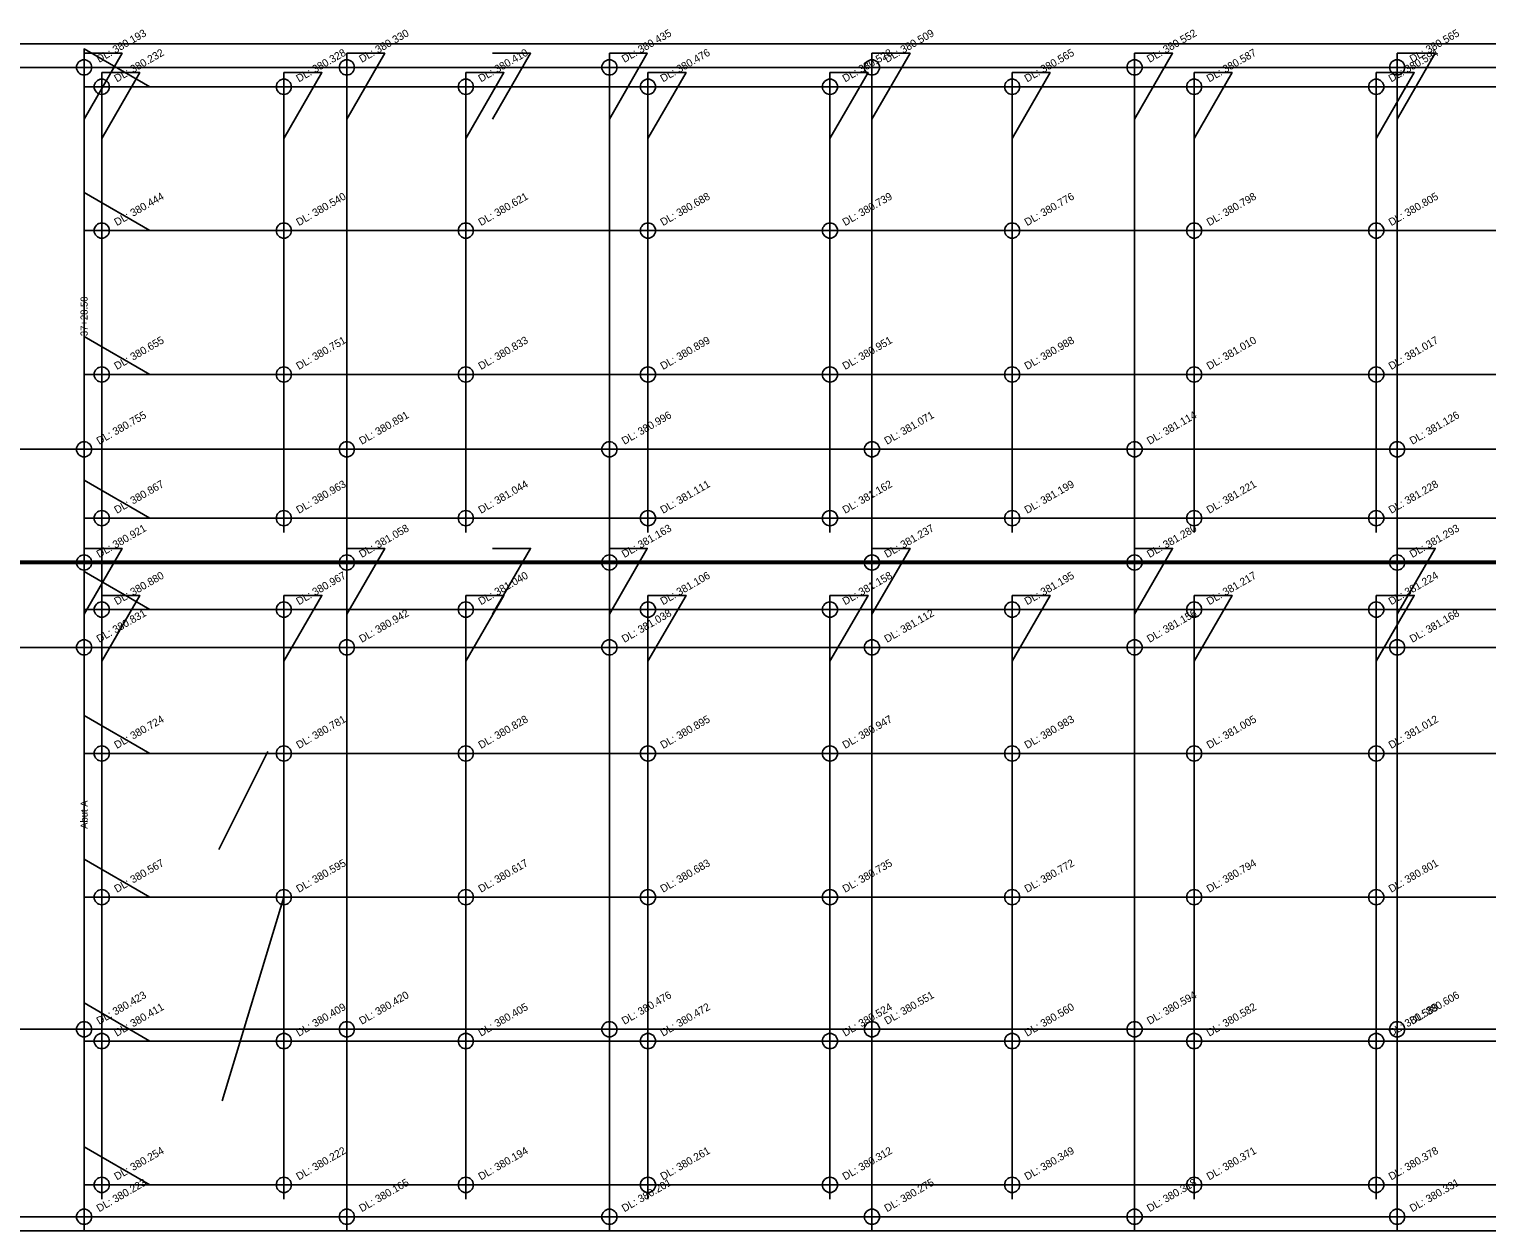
# Model space of a CAD drawing. Extents: x 100440 to 101111, y 50226 to 50315.
# Drawn here: x 100555.6 to 100658.7, y 50225.9 to 50310.8 of the extents above; entities that cross this region are included whole.
import ezdxf

# ---------------------------------------------------------------- set-up
doc = ezdxf.new("R2010")
doc.units = 0
for name, color, linetype in [('Level 1', 7, 'Continuous'), ('Level 10', 7, 'Continuous'), ('Level 21', 7, 'Continuous'), ('Level 23', 7, 'Continuous')]:
    doc.layers.add(name, color=color, linetype=linetype)

msp = doc.modelspace()

# ---------------------------------------------------------------- linework, layer by layer
at = {"layer": 'Level 1'}
for p, q in [((100559.5, 50306.77), (101034.5, 50306.77)), ((100559.5, 50296.6), (101034.5, 50296.6)), ((100560.75, 50288.14), (100560.75, 50258.14)), ((100560.75, 50288.14), (100560.75, 50258.14)), ((100559.5, 50286.43), (101034.5, 50286.43)), ((100559.5, 50276.27), (101034.5, 50276.27)), ((100559.5, 50269.81), (101034.5, 50269.81)), ((100559.5, 50259.64), (101034.5, 50259.64)), ((100559.5, 50249.48), (101034.5, 50249.48)), ((100559.5, 50239.31), (101034.5, 50239.31)), ((100559.5, 50229.14), (101034.5, 50229.14))]:
    msp.add_line(p, q, dxfattribs=at)
for points in [[(100564.16, 50306.77), (100559.5, 50309.45), (100559.5, 50306.77)], [(100564.16, 50296.6), (100559.5, 50299.29), (100559.5, 50296.6)], [(100564.16, 50286.43), (100559.5, 50289.12), (100559.5, 50286.43)], [(100564.16, 50276.27), (100559.5, 50278.95), (100559.5, 50276.27)], [(100564.16, 50269.81), (100559.5, 50272.5), (100559.5, 50269.81)], [(100564.16, 50259.64), (100559.5, 50262.33), (100559.5, 50259.64)], [(100564.16, 50249.48), (100559.5, 50252.16), (100559.5, 50249.48)], [(100564.16, 50239.31), (100559.5, 50242), (100559.5, 50239.31)], [(100564.16, 50229.14), (100559.5, 50231.83), (100559.5, 50229.14)]]:
    msp.add_lwpolyline(points, dxfattribs=at)
at = {"layer": 'Level 10'}
for points in [[(100559.5, 50309.14), (100559.5, 50272.14)], [(100559.5, 50304.49), (100562.19, 50309.14), (100559.5, 50309.14)], [(100578.08, 50309.14), (100578.08, 50272.14)], [(100578.08, 50304.49), (100580.76, 50309.14), (100578.08, 50309.14)], [(100588.39, 50304.49), (100591.08, 50309.14), (100588.39, 50309.14)], [(100596.65, 50309.14), (100596.65, 50272.14)], [(100596.65, 50304.49), (100599.33, 50309.14), (100596.65, 50309.14)], [(100615.22, 50309.14), (100615.22, 50272.14)], [(100615.22, 50304.49), (100617.91, 50309.14), (100615.22, 50309.14)], [(100633.79, 50309.14), (100633.79, 50272.14)], [(100633.79, 50304.49), (100636.48, 50309.14), (100633.79, 50309.14)], [(100652.36, 50309.14), (100652.36, 50272.14)], [(100652.36, 50304.49), (100655.05, 50309.14), (100652.36, 50309.14)], [(100560.75, 50307.77), (100560.75, 50275.27)], [(100560.75, 50303.11), (100563.44, 50307.77), (100560.75, 50307.77)], [(100573.63, 50307.77), (100573.63, 50275.27)], [(100573.63, 50303.11), (100576.32, 50307.77), (100573.63, 50307.77)], [(100586.5, 50307.77), (100586.5, 50275.27)], [(100586.5, 50303.11), (100589.19, 50307.77), (100586.5, 50307.77)], [(100599.38, 50307.77), (100599.38, 50275.27)], [(100599.38, 50303.11), (100602.07, 50307.77), (100599.38, 50307.77)], [(100612.25, 50307.77), (100612.25, 50275.27)], [(100612.25, 50303.11), (100614.94, 50307.77), (100612.25, 50307.77)], [(100625.13, 50307.77), (100625.13, 50275.27)], [(100625.13, 50303.11), (100627.82, 50307.77), (100625.13, 50307.77)], [(100638, 50307.77), (100638, 50275.27)], [(100638, 50303.11), (100640.69, 50307.77), (100638, 50307.77)], [(100650.88, 50307.77), (100650.88, 50275.27)], [(100650.88, 50303.11), (100653.57, 50307.77), (100650.88, 50307.77)], [(100559.5, 50274.14), (100559.5, 50225.89)], [(100559.5, 50269.49), (100562.19, 50274.14), (100559.5, 50274.14)], [(100578.08, 50274.14), (100578.08, 50225.89)], [(100578.08, 50269.49), (100580.76, 50274.14), (100578.08, 50274.14)], [(100588.39, 50269.49), (100591.08, 50274.14), (100588.39, 50274.14)], [(100596.65, 50274.14), (100596.65, 50225.89)], [(100596.65, 50269.49), (100599.33, 50274.14), (100596.65, 50274.14)], [(100615.22, 50274.14), (100615.22, 50225.89)], [(100615.22, 50269.49), (100617.91, 50274.14), (100615.22, 50274.14)], [(100633.79, 50274.14), (100633.79, 50225.89)], [(100633.79, 50269.49), (100636.48, 50274.14), (100633.79, 50274.14)], [(100652.36, 50274.14), (100652.36, 50225.89)], [(100652.36, 50269.49), (100655.05, 50274.14), (100652.36, 50274.14)], [(100560.75, 50270.81), (100560.75, 50228.14)], [(100560.75, 50266.16), (100563.44, 50270.81), (100560.75, 50270.81)], [(100573.63, 50270.81), (100573.63, 50228.14)], [(100573.63, 50266.16), (100576.32, 50270.81), (100573.63, 50270.81)], [(100586.5, 50270.81), (100586.5, 50228.14)], [(100586.5, 50266.16), (100589.19, 50270.81), (100586.5, 50270.81)], [(100599.38, 50270.81), (100599.38, 50228.14)], [(100599.38, 50266.16), (100602.07, 50270.81), (100599.38, 50270.81)], [(100612.25, 50270.81), (100612.25, 50228.14)], [(100612.25, 50266.16), (100614.94, 50270.81), (100612.25, 50270.81)], [(100625.13, 50270.81), (100625.13, 50228.14)], [(100625.13, 50266.16), (100627.82, 50270.81), (100625.13, 50270.81)], [(100638, 50270.81), (100638, 50228.14)], [(100638, 50266.16), (100640.69, 50270.81), (100638, 50270.81)], [(100650.88, 50270.81), (100650.88, 50228.14)], [(100650.88, 50266.16), (100653.57, 50270.81), (100650.88, 50270.81)]]:
    msp.add_lwpolyline(points, dxfattribs=at)
for centre in [(100559.5, 50308.14), (100578.08, 50308.14), (100596.65, 50308.14), (100615.22, 50308.14), (100633.79, 50308.14), (100652.36, 50308.14), (100560.75, 50306.77), (100573.63, 50306.77), (100586.5, 50306.77), (100599.38, 50306.77), (100612.25, 50306.77), (100625.13, 50306.77), (100638, 50306.77), (100650.88, 50306.77), (100560.75, 50296.6), (100573.63, 50296.6), (100586.5, 50296.6), (100599.38, 50296.6), (100612.25, 50296.6), (100625.13, 50296.6), (100638, 50296.6), (100650.88, 50296.6), (100560.75, 50286.43), (100573.63, 50286.43), (100586.5, 50286.43), (100599.38, 50286.43), (100612.25, 50286.43), (100625.13, 50286.43), (100638, 50286.43), (100650.88, 50286.43), (100559.5, 50281.14), (100578.08, 50281.14), (100596.65, 50281.14), (100615.22, 50281.14), (100633.79, 50281.14), (100652.36, 50281.14), (100560.75, 50276.27), (100573.63, 50276.27), (100586.5, 50276.27), (100599.38, 50276.27), (100612.25, 50276.27), (100625.13, 50276.27), (100638, 50276.27), (100650.88, 50276.27), (100559.5, 50273.14), (100559.5, 50273.14), (100578.08, 50273.14), (100578.08, 50273.14), (100596.65, 50273.14), (100596.65, 50273.14), (100615.22, 50273.14), (100615.22, 50273.14), (100633.79, 50273.14), (100633.79, 50273.14), (100652.36, 50273.14), (100652.36, 50273.14), (100560.75, 50269.81), (100573.63, 50269.81), (100586.5, 50269.81), (100599.38, 50269.81), (100612.25, 50269.81), (100625.13, 50269.81), (100638, 50269.81), (100650.88, 50269.81), (100559.5, 50267.14), (100578.08, 50267.14), (100596.65, 50267.14), (100615.22, 50267.14), (100633.79, 50267.14), (100652.36, 50267.14), (100560.75, 50259.64), (100573.63, 50259.64), (100586.5, 50259.64), (100599.38, 50259.64), (100612.25, 50259.64), (100625.13, 50259.64), (100638, 50259.64), (100650.88, 50259.64), (100560.75, 50249.48), (100573.63, 50249.48), (100586.5, 50249.48), (100599.38, 50249.48), (100612.25, 50249.48), (100625.13, 50249.48), (100638, 50249.48), (100650.88, 50249.48), (100559.5, 50240.14), (100578.08, 50240.14), (100596.65, 50240.14), (100615.22, 50240.14), (100633.79, 50240.14), (100652.36, 50240.14), (100560.75, 50239.31), (100573.63, 50239.31), (100586.5, 50239.31), (100599.38, 50239.31), (100612.25, 50239.31), (100625.13, 50239.31), (100638, 50239.31), (100650.88, 50239.31), (100560.75, 50229.14), (100573.63, 50229.14), (100586.5, 50229.14), (100599.38, 50229.14), (100612.25, 50229.14), (100625.13, 50229.14), (100638, 50229.14), (100650.88, 50229.14), (100559.5, 50226.89), (100578.08, 50226.89), (100596.65, 50226.89), (100615.22, 50226.89), (100633.79, 50226.89), (100652.36, 50226.89)]:
    msp.add_circle(centre, 0.537, dxfattribs=at)
at = {"layer": 'Level 23'}
for p, q in [((100439.55, 50309.81), (101111.48, 50309.81)), ((100439.55, 50308.14), (101111.48, 50308.14)), ((100559.5, 50288.14), (100559.5, 50258.14)), ((100559.5, 50288.14), (100559.5, 50258.14)), ((100439.55, 50281.14), (101111.48, 50281.14)), ((100439.55, 50273.23), (101111.48, 50273.23)), ((100439.55, 50273.14), (101111.48, 50273.14)), ((100448.2, 50273.14), (101107.51, 50273.14)), ((100448.2, 50273.06), (101107.51, 50273.06)), ((100448.2, 50267.14), (101107.51, 50267.14)), ((100572.5, 50259.77), (100569.03, 50252.85)), ((100573.63, 50249.48), (100569.26, 50235.09)), ((100448.2, 50240.14), (101107.51, 50240.14)), ((100448.2, 50226.89), (101107.51, 50226.89)), ((100448.2, 50225.89), (101107.51, 50225.89))]:
    msp.add_line(p, q, dxfattribs=at)

# ---------------------------------------------------------------- texts
at = {"layer": 'Level 10'}
for s, p in [('DL: 380.193', (100560.57, 50308.45)), ('DL: 380.330', (100579.14, 50308.45)), ('DL: 380.435', (100597.71, 50308.45)), ('DL: 380.509', (100616.28, 50308.45)), ('DL: 380.552', (100634.85, 50308.45)), ('DL: 380.565', (100653.43, 50308.45)), ('DL: 380.232', (100561.82, 50307.07)), ('DL: 380.328', (100574.69, 50307.07)), ('DL: 380.410', (100587.57, 50307.07)), ('DL: 380.476', (100600.44, 50307.07)), ('DL: 380.528', (100613.32, 50307.07)), ('DL: 380.565', (100626.19, 50307.07)), ('DL: 380.587', (100639.07, 50307.07)), ('DL: 380.594', (100651.94, 50307.07)), ('DL: 380.444', (100561.82, 50296.91)), ('DL: 380.540', (100574.69, 50296.91)), ('DL: 380.621', (100587.57, 50296.91)), ('DL: 380.688', (100600.44, 50296.91)), ('DL: 380.739', (100613.32, 50296.91)), ('DL: 380.776', (100626.19, 50296.91)), ('DL: 380.798', (100639.07, 50296.91)), ('DL: 380.805', (100651.94, 50296.91)), ('DL: 380.655', (100561.82, 50286.74)), ('DL: 380.751', (100574.69, 50286.74)), ('DL: 380.833', (100587.57, 50286.74)), ('DL: 380.899', (100600.44, 50286.74)), ('DL: 380.951', (100613.32, 50286.74)), ('DL: 380.988', (100626.19, 50286.74)), ('DL: 381.010', (100639.07, 50286.74)), ('DL: 381.017', (100651.94, 50286.74)), ('DL: 380.755', (100560.57, 50281.45)), ('DL: 380.891', (100579.14, 50281.45)), ('DL: 380.996', (100597.71, 50281.45)), ('DL: 381.071', (100616.28, 50281.45)), ('DL: 381.114', (100634.85, 50281.45)), ('DL: 381.126', (100653.43, 50281.45)), ('DL: 380.867', (100561.82, 50276.57)), ('DL: 380.963', (100574.69, 50276.57)), ('DL: 381.044', (100587.57, 50276.57)), ('DL: 381.111', (100600.44, 50276.57)), ('DL: 381.162', (100613.32, 50276.57)), ('DL: 381.199', (100626.19, 50276.57)), ('DL: 381.221', (100639.07, 50276.57)), ('DL: 381.228', (100651.94, 50276.57)), ('DL: 380.921', (100560.57, 50273.45)), ('DL: 380.921', (100560.57, 50273.45)), ('DL: 381.058', (100579.14, 50273.45)), ('DL: 381.058', (100579.14, 50273.45)), ('DL: 381.163', (100597.71, 50273.45)), ('DL: 381.163', (100597.71, 50273.45)), ('DL: 381.237', (100616.28, 50273.45)), ('DL: 381.237', (100616.28, 50273.45)), ('DL: 381.280', (100634.85, 50273.45)), ('DL: 381.280', (100634.85, 50273.45)), ('DL: 381.293', (100653.43, 50273.45)), ('DL: 381.293', (100653.43, 50273.45)), ('DL: 380.880', (100561.82, 50270.11)), ('DL: 380.967', (100574.69, 50270.11)), ('DL: 381.040', (100587.57, 50270.11)), ('DL: 381.106', (100600.44, 50270.11)), ('DL: 381.158', (100613.32, 50270.11)), ('DL: 381.195', (100626.19, 50270.11)), ('DL: 381.217', (100639.07, 50270.11)), ('DL: 381.224', (100651.94, 50270.11)), ('DL: 380.831', (100560.57, 50267.45)), ('DL: 380.942', (100579.14, 50267.45)), ('DL: 381.038', (100597.71, 50267.45)), ('DL: 381.112', (100616.28, 50267.45)), ('DL: 381.156', (100634.85, 50267.45)), ('DL: 381.168', (100653.43, 50267.45)), ('DL: 380.724', (100561.82, 50259.95)), ('DL: 380.781', (100574.69, 50259.95)), ('DL: 380.828', (100587.57, 50259.95)), ('DL: 380.895', (100600.44, 50259.95)), ('DL: 380.947', (100613.32, 50259.95)), ('DL: 380.983', (100626.19, 50259.95)), ('DL: 381.005', (100639.07, 50259.95)), ('DL: 381.012', (100651.94, 50259.95)), ('DL: 380.567', (100561.82, 50249.78)), ('DL: 380.595', (100574.69, 50249.78)), ('DL: 380.617', (100587.57, 50249.78)), ('DL: 380.683', (100600.44, 50249.78)), ('DL: 380.735', (100613.32, 50249.78)), ('DL: 380.772', (100626.19, 50249.78)), ('DL: 380.794', (100639.07, 50249.78)), ('DL: 380.801', (100651.94, 50249.78)), ('DL: 380.423', (100560.57, 50240.45)), ('DL: 380.420', (100579.14, 50240.45)), ('DL: 380.476', (100597.71, 50240.45)), ('DL: 380.551', (100616.28, 50240.45)), ('DL: 380.594', (100634.85, 50240.45)), ('DL: 380.606', (100653.43, 50240.45)), ('DL: 380.411', (100561.82, 50239.61)), ('DL: 380.409', (100574.69, 50239.61)), ('DL: 380.405', (100587.57, 50239.61)), ('DL: 380.472', (100600.44, 50239.61)), ('DL: 380.524', (100613.32, 50239.61)), ('DL: 380.560', (100626.19, 50239.61)), ('DL: 380.582', (100639.07, 50239.61)), ('DL: 380.589', (100651.94, 50239.61)), ('DL: 380.254', (100561.82, 50229.45)), ('DL: 380.222', (100574.69, 50229.45)), ('DL: 380.194', (100587.57, 50229.45)), ('DL: 380.261', (100600.44, 50229.45)), ('DL: 380.312', (100613.32, 50229.45)), ('DL: 380.349', (100626.19, 50229.45)), ('DL: 380.371', (100639.07, 50229.45)), ('DL: 380.378', (100651.94, 50229.45)), ('DL: 380.223', (100560.57, 50227.2)), ('DL: 380.165', (100579.14, 50227.2)), ('DL: 380.201', (100597.71, 50227.2)), ('DL: 380.275', (100616.28, 50227.2)), ('DL: 380.318', (100634.85, 50227.2)), ('DL: 380.331', (100653.43, 50227.2))]:
    msp.add_text(s, height=0.5373, rotation=30, dxfattribs=at).set_placement(p)
at = {"layer": 'Level 21'}
for s, p in [('37+28.50', (100559.75, 50289.14)), ('37+28.50', (100559.75, 50289.14)), ('Abut A', (100559.75, 50254.31)), ('Abut A', (100559.75, 50254.31))]:
    msp.add_text(s, height=0.5, rotation=90, dxfattribs=at).set_placement(p)

doc.saveas('drawing.dxf')
